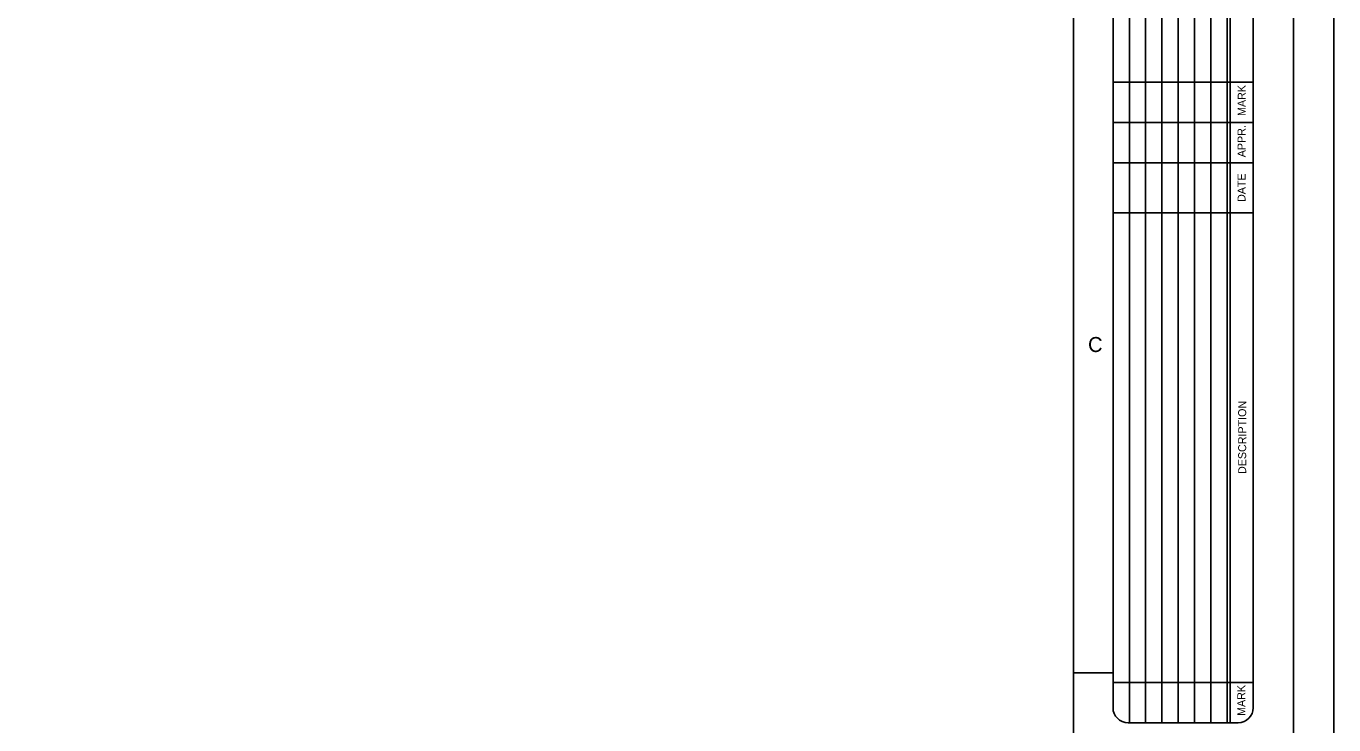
# Model space of a CAD drawing. Extents: x 22339.2 to 22413.4, y 22369.6 to 22418.8.
# Drawn here: x 22391.59 to 22413.39, y 22391.43 to 22403.07 of the extents above; entities that cross this region are included whole.
import ezdxf

# ---------------------------------------------------------------- set-up
doc = ezdxf.new("R2010")
doc.units = 0
for name, color, linetype in [('Level 1', 7, 'Continuous'), ('Level 10', 7, 'Continuous'), ('Level 7', 7, 'Continuous'), ('Level 9', 7, 'Continuous')]:
    doc.layers.add(name, color=color, linetype=linetype)

msp = doc.modelspace()

# ---------------------------------------------------------------- linework, layer by layer
at = {"layer": 'Level 1'}
for p, q in [((22409.978, 22411.461), (22409.978, 22391.461)), ((22410.25, 22411.461), (22410.25, 22391.461)), ((22410.522, 22411.461), (22410.522, 22391.461)), ((22410.794, 22411.461), (22410.794, 22391.461)), ((22411.066, 22411.461), (22411.066, 22391.461)), ((22411.338, 22411.461), (22411.338, 22391.461)), ((22411.61, 22411.461), (22411.61, 22391.461)), ((22411.658, 22411.461), (22411.658, 22391.461)), ((22412.042, 22401.461), (22409.706, 22401.461)), ((22411.792, 22391.461), (22409.956, 22391.461))]:
    msp.add_line(p, q, dxfattribs=at)
msp.add_lwpolyline([(22354.719, 22414.965), (22413.386, 22414.965), (22413.386, 22369.621), (22354.719, 22369.621)], close=True, dxfattribs=at)
for points in [[(22409.706, 22391.711), (22409.706, 22411.211)], [(22412.042, 22391.711), (22412.042, 22411.211)]]:
    msp.add_lwpolyline(points, dxfattribs=at)
for centre, start, end in [((22409.956, 22391.711), 180, 270), ((22411.792, 22391.711), 270, 0)]:
    msp.add_arc(centre, 0.25, start, end, dxfattribs=at)
at = {"layer": 'Level 10'}
msp.add_line((22409.05, 22392.293), (22409.706, 22392.293), dxfattribs=at)
at = {"layer": 'Level 7'}
for p, q in [((22412.042, 22400.789), (22409.706, 22400.789)), ((22412.042, 22399.956), (22409.706, 22399.956)), ((22412.042, 22392.133), (22409.706, 22392.133))]:
    msp.add_line(p, q, dxfattribs=at)
msp.add_lwpolyline([(22412.042, 22402.133), (22409.706, 22402.133)], dxfattribs=at)
at = {"layer": 'Level 9'}
msp.add_line((22412.714, 22370.293), (22412.714, 22414.293), dxfattribs=at)
msp.add_lwpolyline([(22409.05, 22370.293), (22409.05, 22414.293)], dxfattribs=at)

# ---------------------------------------------------------------- texts
at = {"layer": 'Level 1'}
for s, height, p in [('MARK', 0.1333, (22411.917, 22401.57)), ('APPR.', 0.1333, (22411.914, 22400.882)), ('DATE', 0.1333, (22411.914, 22400.137)), ('DESCRIPTION', 0.13333, (22411.925, 22395.605)), ('MARK', 0.1333, (22411.91, 22391.575))]:
    msp.add_text(s, height=height, rotation=90, dxfattribs=at).set_placement(p)
msp.add_text('C', height=0.25, dxfattribs=at).set_placement((22409.29, 22397.637))

doc.saveas('drawing.dxf')
